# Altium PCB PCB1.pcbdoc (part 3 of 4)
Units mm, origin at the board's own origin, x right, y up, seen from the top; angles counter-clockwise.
Board outline 77.9 x 109.02 mm, 4 copper layers (Top Layer, Inner1, Inner2, Bottom Layer); 129 components, 135 nets, 715 pads, 425 vias.
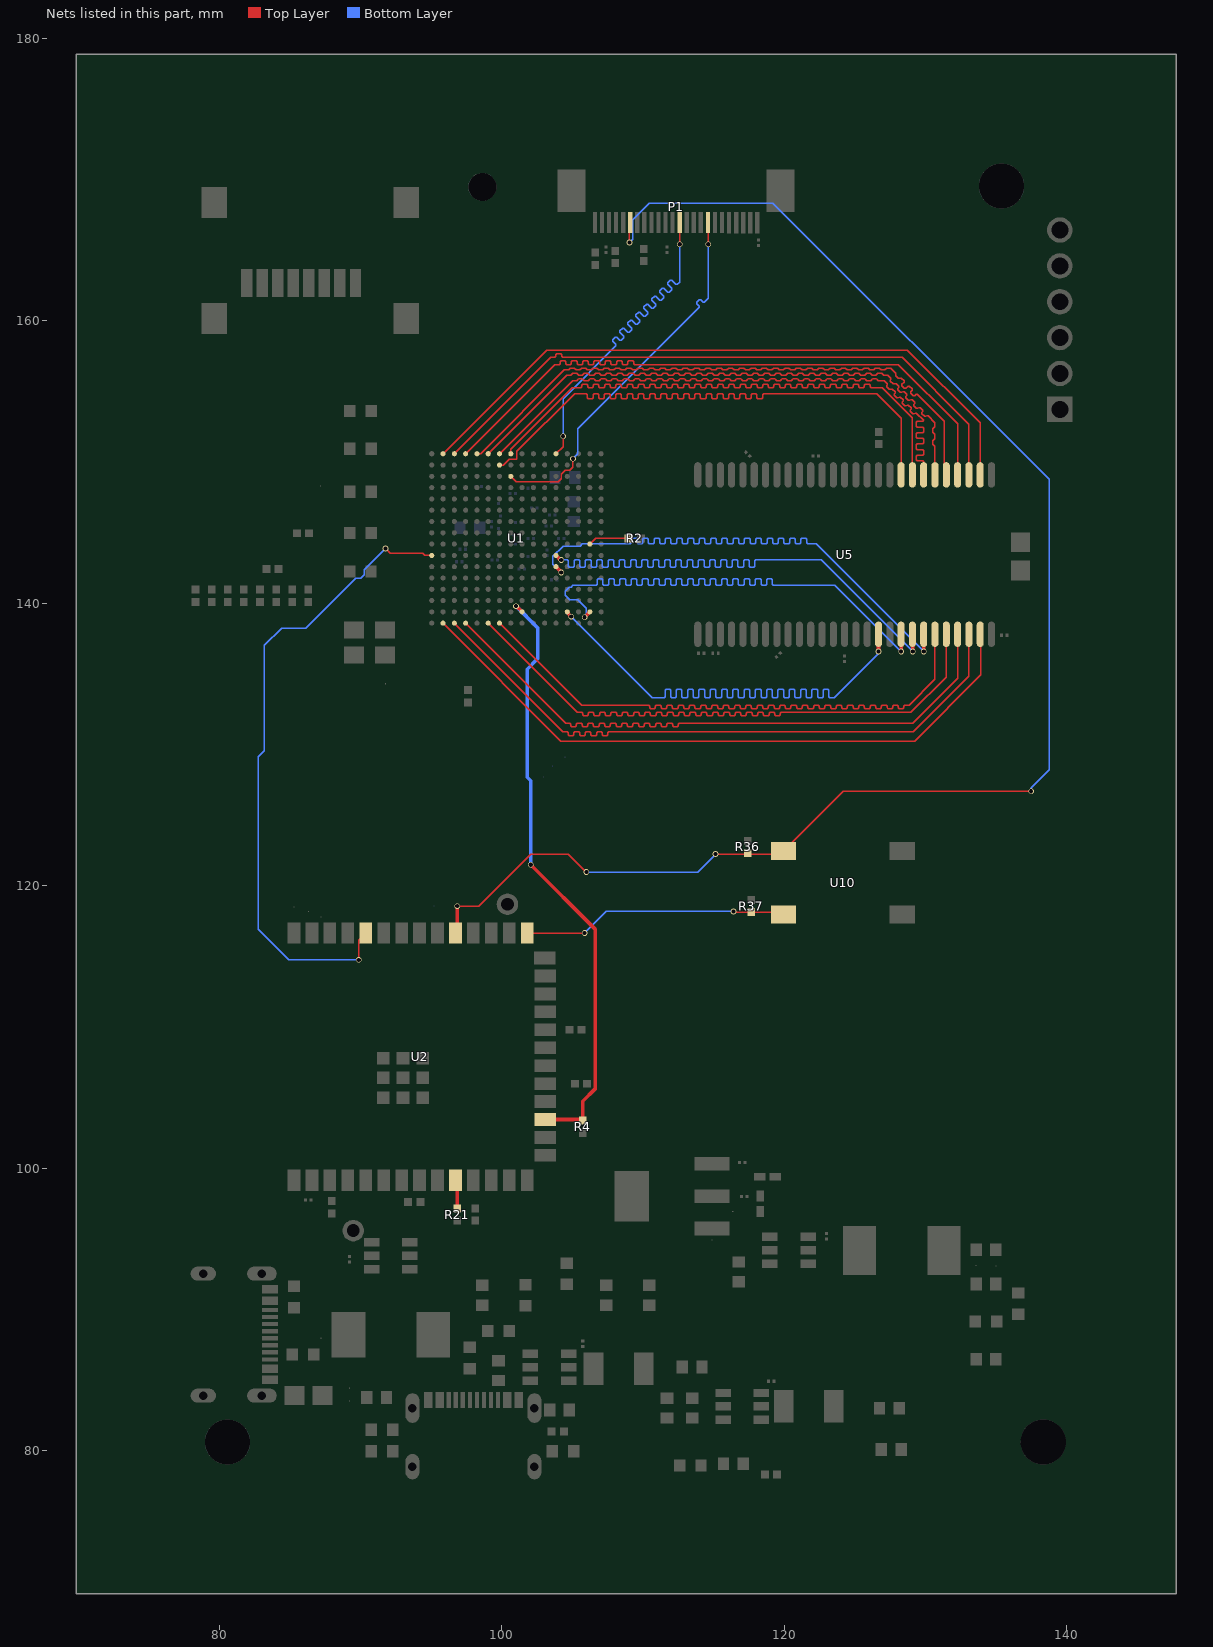
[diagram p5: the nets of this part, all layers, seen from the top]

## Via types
v1: diameter 0.4, hole 0.3, Top Layer to Bottom Layer, 387 vias
v2: diameter 0.5, hole 0.3, Top Layer to Bottom Layer, 36 vias
v3: diameter 1, hole 0.5, Top Layer to Bottom Layer, 2 vias

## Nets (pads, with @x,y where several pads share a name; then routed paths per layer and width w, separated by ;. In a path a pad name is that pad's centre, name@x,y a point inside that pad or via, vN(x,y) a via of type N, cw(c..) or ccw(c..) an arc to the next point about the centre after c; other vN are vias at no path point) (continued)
MCLK: P1.13 U1.A12 | length 27.1
  Top Layer w0.1: U1.A12@103.824,150.585 104.326,151.087 v1(104.326,151.824) ; v1(112.581,165.413) P1.13@112.581,166.951
  Bottom Layer w0.1: v1(104.326,151.824) 104.326,154.491 108.071,158.236 108.071,158.336 107.84,158.567 107.84,158.667 108.023,158.85 108.123,158.85 108.354,158.619 108.454,158.619 108.637,158.802 108.637,158.902 108.356,159.183 108.356,159.283 108.538,159.465 108.638,159.465 108.919,159.184 109.019,159.184 109.202,159.367 109.202,159.467 108.921,159.748 108.921,159.848 109.104,160.031 109.204,160.031 109.485,159.75 109.585,159.75 109.768,159.933 109.768,160.033 109.487,160.314 109.487,160.414 109.67,160.597 109.77,160.597 110.051,160.316 110.151,160.316 110.334,160.499 110.334,160.599 110.053,160.88 110.053,160.98 110.235,161.162 110.335,161.162 110.616,160.881 110.716,160.881 110.899,161.064 110.899,161.164 110.618,161.445 110.618,161.545 110.801,161.728 110.901,161.728 111.182,161.447 111.282,161.447 111.465,161.63 111.465,161.73 111.184,162.011 111.184,162.111 111.367,162.294 111.467,162.294 111.748,162.013 111.848,162.013 112.031,162.196 112.031,162.296 111.75,162.577 111.75,162.677 111.932,162.859 112.032,162.859 112.313,162.578 112.413,162.578 112.581,162.746 v1(112.581,165.413)
PCLK: P1.17 U1.C8 | length 27
  Top Layer w0.1: U1.C8@100.624,148.985 101.006,148.603 103.982,148.603 104.206,148.827 104.206,149.143 104.466,149.403 104.782,149.403 105.006,149.626 105.006,149.943 105.024,149.961 v1(105.024,150.232) ; P1.17@114.581,166.952 114.613,166.92 v1(114.613,165.413)
  Bottom Layer w0.1: v1(105.024,150.232) 105.363,150.571 105.363,152.353 113.952,160.942 113.952,161.042 113.798,161.196 113.798,161.296 113.981,161.479 114.081,161.479 114.235,161.325 114.335,161.325 114.613,161.603 v1(114.613,165.413)
PROGRAM: R37.1 U2.27 U10.3 | length 18.9
  Top Layer w0.1: U2.27@101.781,116.632 105.837,116.632 v1(105.85,116.645) ; v1(116.391,118.169) 116.443,118.117 R37.1@117.661,118.117 119.772,118.117 U10.3@119.938,117.951
  Bottom Layer w0.1: v1(105.85,116.645) 107.374,118.169 v1(116.391,118.169)
PROGRAMN: pad.55@101.786,127.673 R4.2 U1.R9 U2.17 | length 42.9
  Top Layer w0.254: v1(100.987,139.796) 101.013,139.796 U1.R9@101.424,139.385 ; v1(102.04,121.471) 106.59,116.92 106.59,105.591 105.723,104.724 R4.2@105.723,103.362 105.648,103.437 U2.17@103.188,103.437
  Bottom Layer w0.254: v1(100.987,139.796) 102.519,138.264 102.519,136.054 101.786,135.321 pad.55@101.786,127.673 102.04,127.419 v1(102.04,121.471)
RESET: P1.6 R36.1 U2.31 U10.1 | length 110.8
  Top Layer w0.1: v1(96.828,118.55) 98.357,118.55 102.04,122.233 104.707,122.233 v1(105.977,120.963) ; v1(109.025,165.54) 109.025,166.895 P1.6@109.081,166.951 ; v1(115.121,122.233) 119.72,122.233 U10.1@119.938,122.451 124.165,126.678 v1(137.473,126.678)
  Top Layer w0.254: U2.31@96.828,116.632 v1(96.828,118.55)
  Bottom Layer w0.1: v1(105.977,120.963) 113.851,120.963 v1(115.121,122.233) ; v1(109.025,165.54) 109.251,165.766 109.251,167.163 110.422,168.334 119.185,168.334 138.743,148.776 138.743,128.202 137.473,126.932 v1(137.473,126.678)
RX: U1.K1 U2.36 | length 45.5
  Top Layer w0.1: v1(89.848,114.74) 89.848,116.129 U2.36@90.351,116.632 ; v1(91.754,143.878) 92.082,143.55 94.381,143.55 94.546,143.385 U1.K1@95.024,143.385
  Bottom Layer w0.1: v1(89.848,114.74) 84.895,114.74 82.736,116.899 82.736,129.127 83.176,129.567 83.176,137.024 84.387,138.235 86.111,138.235 89.646,141.77 90.014,141.77 90.25,142.005 90.25,142.374 v1(91.754,143.878)
SCL: R21.1 U2.10 | length 1.9
  Top Layer w0.254: U2.10@96.828,99.132 96.833,99.127 R21.1@96.833,97.214
SD_A0: U1.T6 U5.23 | length 45.3
  Top Layer w0.1: U1.T6@99.024,138.585 105.343,132.266 105.643,132.266 105.714,132.195 105.714,132.083 105.784,132.012 106.043,132.012 106.114,132.083 106.114,132.195 106.184,132.266 106.443,132.266 106.514,132.195 106.514,132.083 106.584,132.012 106.843,132.012 106.914,132.083 106.914,132.195 106.984,132.266 107.243,132.266 107.314,132.195 107.314,132.083 107.384,132.012 107.643,132.012 107.714,132.083 107.714,132.195 107.784,132.266 108.043,132.266 108.114,132.195 108.114,132.083 108.184,132.012 108.443,132.012 108.514,132.083 108.514,132.195 108.584,132.266 108.843,132.266 108.914,132.195 108.914,132.083 108.984,132.012 109.243,132.012 109.314,132.083 109.314,132.195 109.384,132.266 109.643,132.266 109.714,132.195 109.714,132.083 109.784,132.012 110.043,132.012 110.114,132.083 110.114,132.195 110.184,132.266 110.443,132.266 110.514,132.195 110.514,132.083 110.584,132.012 110.843,132.012 110.914,132.083 110.914,132.195 110.984,132.266 111.243,132.266 111.314,132.195 111.314,132.083 111.384,132.012 111.643,132.012 111.714,132.083 111.714,132.195 111.784,132.266 112.043,132.266 112.114,132.195 112.114,132.083 112.184,132.012 112.443,132.012 112.514,132.083 112.514,132.195 112.584,132.266 112.843,132.266 112.914,132.195 112.914,132.083 112.984,132.012 113.243,132.012 113.314,132.083 113.314,132.195 113.384,132.266 113.643,132.266 113.714,132.195 113.714,132.083 113.784,132.012 114.043,132.012 114.114,132.083 114.114,132.195 114.184,132.266 114.443,132.266 114.514,132.195 114.514,132.083 114.584,132.012 114.843,132.012 114.914,132.083 114.914,132.195 114.984,132.266 115.243,132.266 115.314,132.195 115.314,132.083 115.384,132.012 115.643,132.012 115.714,132.083 115.714,132.195 115.784,132.266 116.043,132.266 116.114,132.195 116.114,132.083 116.184,132.012 116.443,132.012 116.514,132.083 116.514,132.195 116.584,132.266 116.843,132.266 116.914,132.195 116.914,132.083 116.984,132.012 117.243,132.012 117.314,132.083 117.314,132.195 117.384,132.266 117.643,132.266 117.714,132.195 117.714,132.083 117.784,132.012 118.043,132.012 118.114,132.083 118.114,132.195 118.184,132.266 118.443,132.266 118.514,132.195 118.514,132.083 118.584,132.012 118.843,132.012 118.914,132.083 118.914,132.195 118.984,132.266 119.243,132.266 119.314,132.195 119.314,132.083 119.384,132.012 119.643,132.012 119.714,132.083 119.714,132.195 119.784,132.266 128.964,132.266 131.465,134.767 U5.23@131.465,137.8
SD_A1: U1.T4 U5.24 | length 45.6
  Top Layer w0.1: U1.T4@97.424,138.585 104.505,131.504 104.805,131.504 104.876,131.433 104.876,131.321 104.946,131.25 105.205,131.25 105.276,131.321 105.276,131.433 105.346,131.504 105.605,131.504 105.676,131.433 105.676,131.321 105.746,131.25 106.005,131.25 106.076,131.321 106.076,131.433 106.146,131.504 106.405,131.504 106.476,131.433 106.476,131.321 106.546,131.25 106.805,131.25 106.876,131.321 106.876,131.433 106.946,131.504 107.205,131.504 107.276,131.433 107.276,131.321 107.346,131.25 107.605,131.25 107.676,131.321 107.676,131.433 107.746,131.504 108.005,131.504 108.076,131.433 108.076,131.321 108.146,131.25 108.405,131.25 108.476,131.321 108.476,131.433 108.546,131.504 108.805,131.504 108.876,131.433 108.876,131.321 108.946,131.25 109.205,131.25 109.276,131.321 109.276,131.433 109.346,131.504 109.605,131.504 109.676,131.433 109.676,131.321 109.746,131.25 110.005,131.25 110.076,131.321 110.076,131.433 110.146,131.504 110.405,131.504 110.476,131.433 110.476,131.321 110.546,131.25 110.805,131.25 110.876,131.321 110.876,131.433 110.946,131.504 111.205,131.504 111.276,131.433 111.276,131.321 111.346,131.25 111.605,131.25 111.676,131.321 111.676,131.433 111.746,131.504 112.005,131.504 112.076,131.433 112.076,131.321 112.146,131.25 112.405,131.25 112.476,131.321 112.476,131.433 112.546,131.504 129.091,131.504 132.266,134.679 U5.24@132.266,137.799
SD_A2: U1.T3 U5.25 | length 45.9
  Top Layer w0.1: U1.T3@96.624,138.585 104.303,130.906 104.626,130.906 104.697,130.835 104.697,130.686 104.767,130.615 105.026,130.615 105.097,130.686 105.097,130.835 105.167,130.906 105.426,130.906 105.497,130.835 105.497,130.686 105.567,130.615 105.826,130.615 105.897,130.686 105.897,130.835 105.967,130.906 106.226,130.906 106.297,130.835 106.297,130.686 106.367,130.615 106.626,130.615 106.697,130.686 106.697,130.835 106.767,130.906 107.026,130.906 107.097,130.835 107.097,130.686 107.167,130.615 107.426,130.615 107.497,130.686 107.497,130.835 107.567,130.906 129.128,130.906 133.065,134.843 U5.25@133.065,137.8
SD_A3: U1.T2 U5.26 | length 46.4
  Top Layer w0.1: U1.T2@95.824,138.585 104.175,130.234 129.218,130.234 133.917,134.933 133.917,137.748 U5.26@133.865,137.8
SD_A4: U1.A2 U5.29 | length 46.9
  Top Layer w0.1: U1.A2@95.824,150.585 103.159,157.92 128.71,157.92 133.865,152.765 U5.29@133.865,149.084
SD_A5: U1.A3 U5.30 | length 45.2
  Top Layer w0.1: U1.A3@96.624,150.585 103.451,157.412 103.751,157.412 103.821,157.483 103.821,157.595 103.892,157.666 104.151,157.666 104.221,157.595 104.221,157.483 104.292,157.412 128.329,157.412 133.065,152.676 U5.30@133.065,149.084
SD_A6: U1.A4 U5.31 | length 45.2
  Top Layer w0.1: U1.A4@97.424,150.585 103.743,156.904 104.043,156.904 104.114,156.975 104.114,157.087 104.184,157.158 104.443,157.158 104.514,157.087 104.514,156.975 104.584,156.904 104.843,156.904 104.914,156.975 104.914,157.087 104.984,157.158 105.243,157.158 105.314,157.087 105.314,156.975 105.384,156.904 105.643,156.904 105.714,156.975 105.714,157.087 105.784,157.158 106.043,157.158 106.114,157.087 106.114,156.975 106.184,156.904 106.443,156.904 106.514,156.975 106.514,157.087 106.584,157.158 106.843,157.158 106.914,157.087 106.914,156.975 106.984,156.904 107.243,156.904 107.314,156.975 107.314,157.087 107.384,157.158 107.643,157.158 107.714,157.087 107.714,156.975 107.784,156.904 108.043,156.904 108.114,156.975 108.114,157.087 108.184,157.158 108.443,157.158 108.514,157.087 108.514,156.975 108.584,156.904 108.843,156.904 108.914,156.975 108.914,157.087 108.984,157.158 109.243,157.158 109.314,157.087 109.314,156.975 109.384,156.904 128.075,156.904 132.265,152.714 U5.31@132.265,149.084
SD_A7: U1.A5 U5.32 | length 45.1
  Top Layer w0.1: U1.A5@98.224,150.585 98.484,150.585 104.422,156.523 104.722,156.523 104.849,156.65 105.122,156.65 105.249,156.523 105.522,156.523 105.649,156.65 105.922,156.65 106.049,156.523 106.322,156.523 106.449,156.65 106.722,156.65 106.849,156.523 107.122,156.523 107.249,156.65 107.522,156.65 107.649,156.523 107.922,156.523 108.049,156.65 108.322,156.65 108.449,156.523 108.722,156.523 108.849,156.65 109.122,156.65 109.249,156.523 109.522,156.523 109.649,156.65 109.922,156.65 110.049,156.523 110.322,156.523 110.449,156.65 110.722,156.65 110.849,156.523 111.122,156.523 111.249,156.65 111.522,156.65 111.649,156.523 111.922,156.523 112.049,156.65 112.322,156.65 112.449,156.523 112.722,156.523 112.849,156.65 113.122,156.65 113.249,156.523 113.522,156.523 113.649,156.65 113.922,156.65 114.049,156.523 114.322,156.523 114.449,156.65 114.722,156.65 114.849,156.523 115.122,156.523 115.249,156.65 115.522,156.65 115.649,156.523 115.922,156.523 116.049,156.65 116.322,156.65 116.449,156.523 116.722,156.523 116.849,156.65 117.122,156.65 117.249,156.523 117.522,156.523 117.649,156.65 117.922,156.65 118.049,156.523 118.322,156.523 118.449,156.65 118.722,156.65 118.849,156.523 119.122,156.523 119.249,156.65 119.522,156.65 119.649,156.523 119.922,156.523 120.049,156.65 120.322,156.65 120.449,156.523 120.722,156.523 120.849,156.65 121.122,156.65 121.249,156.523 121.522,156.523 121.649,156.65 121.922,156.65 122.049,156.523 122.322,156.523 122.449,156.65 122.722,156.65 122.849,156.523 123.122,156.523 123.249,156.65 123.522,156.65 123.649,156.523 123.922,156.523 124.049,156.65 124.322,156.65 124.449,156.523 124.722,156.523 124.849,156.65 125.122,156.65 125.249,156.523 125.522,156.523 125.649,156.65 125.922,156.65 126.049,156.523 126.322,156.523 126.449,156.65 126.722,156.65 126.849,156.523 127.122,156.523 127.249,156.65 127.522,156.65 127.894,156.278 127.894,156.099 128.077,155.916 128.177,155.916 128.189,155.928 128.289,155.928 128.472,155.745 128.472,155.645 128.317,155.491 128.317,155.391 128.5,155.208 128.6,155.208 128.754,155.362 128.854,155.362 129.037,155.179 129.037,155.079 128.932,154.974 128.932,154.874 129.114,154.691 129.214,154.691 129.32,154.796 129.42,154.796 131.338,152.879 131.338,149.211 U5.32@131.465,149.084
SD_A8: U1.A6 U5.33 | length 44.4
  Top Layer w0.1: U1.A6@99.024,150.585 104.581,156.142 104.881,156.142 104.952,156.213 104.952,156.223 105.022,156.294 105.281,156.294 105.352,156.223 105.352,156.213 105.422,156.142 105.681,156.142 105.752,156.213 105.752,156.223 105.822,156.294 106.081,156.294 106.152,156.223 106.152,156.213 106.222,156.142 106.481,156.142 106.552,156.213 106.552,156.223 106.622,156.294 106.881,156.294 106.952,156.223 106.952,156.213 107.022,156.142 107.281,156.142 107.352,156.213 107.352,156.223 107.422,156.294 107.681,156.294 107.752,156.223 107.752,156.213 107.822,156.142 108.081,156.142 108.152,156.213 108.152,156.223 108.222,156.294 108.481,156.294 108.552,156.223 108.552,156.213 108.622,156.142 108.881,156.142 108.952,156.213 108.952,156.223 109.022,156.294 109.281,156.294 109.352,156.223 109.352,156.213 109.422,156.142 109.681,156.142 109.752,156.213 109.752,156.223 109.822,156.294 110.081,156.294 110.152,156.223 110.152,156.213 110.222,156.142 110.481,156.142 110.552,156.213 110.552,156.223 110.622,156.294 110.881,156.294 110.952,156.223 110.952,156.213 111.022,156.142 111.281,156.142 111.352,156.213 111.352,156.223 111.422,156.294 111.681,156.294 111.752,156.223 111.752,156.213 111.822,156.142 112.081,156.142 112.152,156.213 112.152,156.223 112.222,156.294 112.481,156.294 112.552,156.223 112.552,156.213 112.622,156.142 112.881,156.142 112.952,156.213 112.952,156.223 113.022,156.294 113.281,156.294 113.352,156.223 113.352,156.213 113.422,156.142 113.681,156.142 113.752,156.213 113.752,156.223 113.822,156.294 114.081,156.294 114.152,156.223 114.152,156.213 114.222,156.142 114.481,156.142 114.552,156.213 114.552,156.223 114.622,156.294 114.881,156.294 114.952,156.223 114.952,156.213 115.022,156.142 115.281,156.142 115.352,156.213 115.352,156.223 115.422,156.294 115.681,156.294 115.752,156.223 115.752,156.213 115.822,156.142 116.081,156.142 116.152,156.213 116.152,156.223 116.222,156.294 116.481,156.294 116.552,156.223 116.552,156.213 116.622,156.142 116.881,156.142 116.952,156.213 116.952,156.223 117.022,156.294 117.281,156.294 117.352,156.223 117.352,156.213 117.422,156.142 117.681,156.142 117.752,156.213 117.752,156.223 117.822,156.294 118.081,156.294 118.152,156.223 118.152,156.213 118.222,156.142 118.481,156.142 118.552,156.213 118.552,156.223 118.622,156.294 118.881,156.294 118.952,156.223 118.952,156.213 119.022,156.142 119.281,156.142 119.352,156.213 119.352,156.223 119.422,156.294 119.681,156.294 119.752,156.223 119.752,156.213 119.822,156.142 120.081,156.142 120.152,156.213 120.152,156.223 120.222,156.294 120.481,156.294 120.552,156.223 120.552,156.213 120.622,156.142 120.881,156.142 120.952,156.213 120.952,156.223 121.022,156.294 121.281,156.294 121.352,156.223 121.352,156.213 121.422,156.142 121.681,156.142 121.752,156.213 121.752,156.223 121.822,156.294 122.081,156.294 122.152,156.223 122.152,156.213 122.222,156.142 122.481,156.142 122.552,156.213 122.552,156.223 122.622,156.294 122.881,156.294 122.952,156.223 122.952,156.213 123.022,156.142 123.281,156.142 123.352,156.213 123.352,156.223 123.422,156.294 123.681,156.294 123.752,156.223 123.752,156.213 123.822,156.142 124.081,156.142 124.152,156.213 124.152,156.223 124.222,156.294 124.481,156.294 124.552,156.223 124.552,156.213 124.622,156.142 124.881,156.142 124.952,156.213 124.952,156.223 125.022,156.294 125.281,156.294 125.352,156.223 125.352,156.213 125.422,156.142 125.681,156.142 125.752,156.213 125.752,156.223 125.822,156.294 126.081,156.294 126.152,156.223 126.152,156.213 126.222,156.142 126.481,156.142 126.552,156.213 126.552,156.223 126.622,156.294 126.881,156.294 126.952,156.223 126.952,156.213 127.022,156.142 127.313,156.142 127.525,155.93 127.525,155.83 127.513,155.818 127.513,155.718 127.696,155.535 127.796,155.535 127.808,155.547 127.908,155.547 128.091,155.364 128.091,155.264 128.035,155.209 128.035,155.109 128.218,154.926 128.318,154.926 128.373,154.981 128.473,154.981 128.656,154.798 128.656,154.698 128.601,154.643 128.601,154.543 128.784,154.36 128.884,154.36 128.939,154.415 129.039,154.415 129.222,154.233 129.222,154.133 129.167,154.077 129.167,153.977 129.349,153.794 129.449,153.794 129.505,153.85 129.605,153.85 129.788,153.667 129.788,153.567 129.741,153.52 129.741,153.42 129.924,153.238 130.024,153.238 130.071,153.284 130.171,153.284 130.665,152.79 130.665,152.49 130.594,152.419 130.577,152.419 130.506,152.348 130.506,152.09 130.577,152.019 130.594,152.019 130.665,151.948 130.665,151.648 130.594,151.578 130.577,151.578 130.506,151.507 130.506,151.248 130.577,151.178 130.594,151.178 130.665,151.107 U5.33@130.665,149.084
SD_A9: U1.A7 U5.34 | length 45.4
  Top Layer w0.1: U1.A7@99.824,150.585 105,155.761 105.3,155.761 105.371,155.832 105.371,155.842 105.441,155.913 105.7,155.913 105.771,155.842 105.771,155.832 105.841,155.761 106.1,155.761 106.171,155.832 106.171,155.842 106.241,155.913 106.5,155.913 106.571,155.842 106.571,155.832 106.641,155.761 106.9,155.761 106.971,155.832 106.971,155.842 107.041,155.913 107.3,155.913 107.371,155.842 107.371,155.832 107.441,155.761 107.7,155.761 107.771,155.832 107.771,155.842 107.841,155.913 108.1,155.913 108.171,155.842 108.171,155.832 108.241,155.761 108.5,155.761 108.571,155.832 108.571,155.842 108.641,155.913 108.9,155.913 108.971,155.842 108.971,155.832 109.041,155.761 109.3,155.761 109.371,155.832 109.371,155.842 109.441,155.913 109.7,155.913 109.771,155.842 109.771,155.832 109.841,155.761 110.1,155.761 110.171,155.832 110.171,155.842 110.241,155.913 110.5,155.913 110.571,155.842 110.571,155.832 110.641,155.761 110.9,155.761 110.971,155.832 110.971,155.842 111.041,155.913 111.3,155.913 111.371,155.842 111.371,155.832 111.441,155.761 111.7,155.761 111.771,155.832 111.771,155.842 111.841,155.913 112.1,155.913 112.171,155.842 112.171,155.832 112.241,155.761 112.5,155.761 112.571,155.832 112.571,155.842 112.641,155.913 112.9,155.913 112.971,155.842 112.971,155.832 113.041,155.761 113.3,155.761 113.371,155.832 113.371,155.842 113.441,155.913 113.7,155.913 113.771,155.842 113.771,155.832 113.841,155.761 114.1,155.761 114.171,155.832 114.171,155.842 114.241,155.913 114.5,155.913 114.571,155.842 114.571,155.832 114.641,155.761 114.9,155.761 114.971,155.832 114.971,155.842 115.041,155.913 115.3,155.913 115.371,155.842 115.371,155.832 115.441,155.761 115.7,155.761 115.771,155.832 115.771,155.842 115.841,155.913 116.1,155.913 116.171,155.842 116.171,155.832 116.241,155.761 116.5,155.761 116.571,155.832 116.571,155.842 116.641,155.913 116.9,155.913 116.971,155.842 116.971,155.832 117.041,155.761 117.3,155.761 117.371,155.832 117.371,155.842 117.441,155.913 117.7,155.913 117.771,155.842 117.771,155.832 117.841,155.761 118.1,155.761 118.171,155.832 118.171,155.842 118.241,155.913 118.5,155.913 118.571,155.842 118.571,155.832 118.641,155.761 118.9,155.761 118.971,155.832 118.971,155.842 119.041,155.913 119.3,155.913 119.371,155.842 119.371,155.832 119.441,155.761 119.7,155.761 119.771,155.832 119.771,155.842 119.841,155.913 120.1,155.913 120.171,155.842 120.171,155.832 120.241,155.761 120.5,155.761 120.571,155.832 120.571,155.842 120.641,155.913 120.9,155.913 120.971,155.842 120.971,155.832 121.041,155.761 121.3,155.761 121.371,155.832 121.371,155.842 121.441,155.913 121.7,155.913 121.771,155.842 121.771,155.832 121.841,155.761 122.1,155.761 122.171,155.832 122.171,155.842 122.241,155.913 122.5,155.913 122.571,155.842 122.571,155.832 122.641,155.761 122.9,155.761 122.971,155.832 122.971,155.842 123.041,155.913 123.3,155.913 123.371,155.842 123.371,155.832 123.441,155.761 123.7,155.761 123.771,155.832 123.771,155.842 123.841,155.913 124.1,155.913 124.171,155.842 124.171,155.832 124.241,155.761 124.5,155.761 124.571,155.832 124.571,155.842 124.641,155.913 124.9,155.913 124.971,155.842 124.971,155.832 125.041,155.761 125.3,155.761 125.371,155.832 125.371,155.842 125.441,155.913 125.7,155.913 125.771,155.842 125.771,155.832 125.841,155.761 126.1,155.761 126.171,155.832 126.171,155.842 126.241,155.913 126.5,155.913 126.571,155.842 126.571,155.832 126.641,155.761 127.059,155.761 127.271,155.549 127.271,155.449 127.259,155.437 127.259,155.337 127.442,155.154 127.542,155.154 127.554,155.166 127.654,155.166 127.837,154.983 127.837,154.883 127.781,154.828 127.781,154.728 127.964,154.545 128.064,154.545 128.119,154.6 128.219,154.6 128.402,154.417 128.402,154.317 128.347,154.262 128.347,154.162 128.53,153.979 128.63,153.979 128.685,154.034 128.785,154.034 128.968,153.852 128.968,153.752 128.913,153.696 128.913,153.596 129.095,153.413 129.195,153.413 129.251,153.469 129.351,153.469 129.865,152.955 129.865,152.947 129.794,152.876 129.416,152.876 129.345,152.805 129.345,152.547 129.416,152.476 129.794,152.476 129.865,152.405 129.865,152.147 129.794,152.076 129.416,152.076 129.345,152.005 129.345,151.747 129.416,151.676 129.794,151.676 129.865,151.605 129.865,151.347 129.794,151.276 129.416,151.276 129.345,151.205 129.345,150.947 129.416,150.876 129.794,150.876 129.865,150.805 129.865,150.547 129.794,150.476 129.416,150.476 129.345,150.405 129.345,150.147 129.416,150.076 129.794,150.076 129.865,150.005 U5.34@129.865,149.084
SD_A10: U1.T7 U5.22 | length 45.1
  Top Layer w0.1: U1.T7@99.824,138.585 105.635,132.774 110.395,132.774 110.466,132.703 110.466,132.591 110.537,132.52 110.795,132.52 110.866,132.591 110.866,132.703 110.937,132.774 111.195,132.774 111.266,132.703 111.266,132.591 111.337,132.52 111.595,132.52 111.666,132.591 111.666,132.703 111.737,132.774 111.995,132.774 112.066,132.703 112.066,132.591 112.137,132.52 112.395,132.52 112.466,132.591 112.466,132.703 112.537,132.774 112.795,132.774 112.866,132.703 112.866,132.591 112.937,132.52 113.195,132.52 113.266,132.591 113.266,132.703 113.337,132.774 113.595,132.774 113.666,132.703 113.666,132.591 113.737,132.52 113.995,132.52 114.066,132.591 114.066,132.703 114.137,132.774 114.395,132.774 114.466,132.703 114.466,132.591 114.537,132.52 114.795,132.52 114.866,132.591 114.866,132.703 114.937,132.774 115.195,132.774 115.266,132.703 115.266,132.591 115.337,132.52 115.595,132.52 115.666,132.591 115.666,132.703 115.737,132.774 115.995,132.774 116.066,132.703 116.066,132.591 116.137,132.52 116.395,132.52 116.466,132.591 116.466,132.703 116.537,132.774 116.795,132.774 116.866,132.703 116.866,132.591 116.937,132.52 117.195,132.52 117.266,132.591 117.266,132.703 117.337,132.774 117.595,132.774 117.666,132.703 117.666,132.591 117.737,132.52 117.995,132.52 118.066,132.591 118.066,132.703 118.137,132.774 118.395,132.774 118.466,132.703 118.466,132.591 118.537,132.52 118.795,132.52 118.866,132.591 118.866,132.703 118.937,132.774 119.195,132.774 119.266,132.703 119.266,132.591 119.337,132.52 119.595,132.52 119.666,132.591 119.666,132.703 119.737,132.774 119.995,132.774 120.066,132.703 120.066,132.591 120.137,132.52 120.395,132.52 120.466,132.591 120.466,132.703 120.537,132.774 120.795,132.774 120.866,132.703 120.866,132.591 120.937,132.52 121.195,132.52 121.266,132.591 121.266,132.703 121.337,132.774 121.595,132.774 121.666,132.703 121.666,132.591 121.737,132.52 121.995,132.52 122.066,132.591 122.066,132.703 122.137,132.774 122.395,132.774 122.466,132.703 122.466,132.591 122.537,132.52 122.795,132.52 122.866,132.591 122.866,132.703 122.937,132.774 123.195,132.774 123.266,132.703 123.266,132.591 123.337,132.52 123.595,132.52 123.666,132.591 123.666,132.703 123.737,132.774 123.995,132.774 124.066,132.703 124.066,132.591 124.137,132.52 124.395,132.52 124.466,132.591 124.466,132.703 124.537,132.774 124.795,132.774 124.866,132.703 124.866,132.591 124.937,132.52 125.195,132.52 125.266,132.591 125.266,132.703 125.337,132.774 125.595,132.774 125.666,132.703 125.666,132.591 125.737,132.52 125.995,132.52 126.066,132.591 126.066,132.703 126.137,132.774 126.395,132.774 126.466,132.703 126.466,132.591 126.537,132.52 126.795,132.52 126.866,132.591 126.866,132.703 126.937,132.774 127.195,132.774 127.266,132.703 127.266,132.591 127.337,132.52 127.595,132.52 127.666,132.591 127.666,132.703 127.737,132.774 127.995,132.774 128.066,132.703 128.066,132.591 128.137,132.52 128.395,132.52 128.466,132.591 128.466,132.703 128.537,132.774 128.837,132.774 130.665,134.602 U5.22@130.665,137.8
SD_A11: U1.A8 U5.35 | length 44.4
  Top Layer w0.1: U1.A8@100.624,150.585 100.624,150.916 104.961,155.253 105.592,155.253 105.662,155.324 105.662,155.436 105.733,155.507 105.992,155.507 106.062,155.436 106.062,155.324 106.133,155.253 106.392,155.253 106.462,155.324 106.462,155.436 106.533,155.507 106.792,155.507 106.862,155.436 106.862,155.324 106.933,155.253 107.192,155.253 107.262,155.324 107.262,155.436 107.333,155.507 107.592,155.507 107.662,155.436 107.662,155.324 107.733,155.253 107.992,155.253 108.062,155.324 108.062,155.436 108.133,155.507 108.392,155.507 108.462,155.436 108.462,155.324 108.533,155.253 108.792,155.253 108.862,155.324 108.862,155.436 108.933,155.507 109.192,155.507 109.262,155.436 109.262,155.324 109.333,155.253 109.592,155.253 109.662,155.324 109.662,155.436 109.733,155.507 109.992,155.507 110.062,155.436 110.062,155.324 110.133,155.253 110.392,155.253 110.462,155.324 110.462,155.436 110.533,155.507 110.792,155.507 110.862,155.436 110.862,155.324 110.933,155.253 111.192,155.253 111.262,155.324 111.262,155.436 111.333,155.507 111.592,155.507 111.662,155.436 111.662,155.324 111.733,155.253 111.992,155.253 112.062,155.324 112.062,155.436 112.133,155.507 112.392,155.507 112.462,155.436 112.462,155.324 112.533,155.253 112.792,155.253 112.862,155.324 112.862,155.436 112.933,155.507 113.192,155.507 113.262,155.436 113.262,155.324 113.333,155.253 113.592,155.253 113.662,155.324 113.662,155.436 113.733,155.507 113.992,155.507 114.062,155.436 114.062,155.324 114.133,155.253 114.392,155.253 114.462,155.324 114.462,155.436 114.533,155.507 114.792,155.507 114.862,155.436 114.862,155.324 114.933,155.253 115.192,155.253 115.262,155.324 115.262,155.436 115.333,155.507 115.592,155.507 115.662,155.436 115.662,155.324 115.733,155.253 115.992,155.253 116.062,155.324 116.062,155.436 116.133,155.507 116.392,155.507 116.462,155.436 116.462,155.324 116.533,155.253 116.792,155.253 116.862,155.324 116.862,155.436 116.933,155.507 117.192,155.507 117.262,155.436 117.262,155.324 117.333,155.253 117.592,155.253 117.662,155.324 117.662,155.436 117.733,155.507 117.992,155.507 118.062,155.436 118.062,155.324 118.133,155.253 118.392,155.253 118.462,155.324 118.462,155.436 118.533,155.507 118.792,155.507 118.862,155.436 118.862,155.324 118.933,155.253 119.192,155.253 119.262,155.324 119.262,155.436 119.333,155.507 119.592,155.507 119.662,155.436 119.662,155.324 119.733,155.253 119.992,155.253 120.062,155.324 120.062,155.436 120.133,155.507 120.392,155.507 120.462,155.436 120.462,155.324 120.533,155.253 120.792,155.253 120.862,155.324 120.862,155.436 120.933,155.507 121.192,155.507 121.262,155.436 121.262,155.324 121.333,155.253 121.592,155.253 121.662,155.324 121.662,155.436 121.733,155.507 121.992,155.507 122.062,155.436 122.062,155.324 122.133,155.253 122.392,155.253 122.462,155.324 122.462,155.436 122.533,155.507 122.792,155.507 122.862,155.436 122.862,155.324 122.933,155.253 123.192,155.253 123.262,155.324 123.262,155.436 123.333,155.507 123.592,155.507 123.662,155.436 123.662,155.324 123.733,155.253 123.992,155.253 124.062,155.324 124.062,155.436 124.133,155.507 124.392,155.507 124.462,155.436 124.462,155.324 124.533,155.253 124.792,155.253 124.862,155.324 124.862,155.436 124.933,155.507 125.192,155.507 125.262,155.436 125.262,155.324 125.333,155.253 125.592,155.253 125.662,155.324 125.662,155.436 125.733,155.507 125.992,155.507 126.062,155.436 126.062,155.324 126.133,155.253 126.932,155.253 129.065,153.12 U5.35@129.065,149.084
SD_A12: U1.B7 U5.36 | length 45.1
  Top Layer w0.1: U1.B7@99.824,149.785 100.084,149.785 100.502,150.203 101.016,150.203 101.042,150.228 101.042,150.743 105.144,154.845 105.984,154.845 106.055,154.774 106.055,154.535 106.125,154.464 106.384,154.464 106.455,154.535 106.455,154.774 106.525,154.845 106.784,154.845 106.855,154.774 106.855,154.535 106.925,154.464 107.184,154.464 107.255,154.535 107.255,154.774 107.325,154.845 107.584,154.845 107.655,154.774 107.655,154.535 107.725,154.464 107.984,154.464 108.055,154.535 108.055,154.774 108.125,154.845 108.384,154.845 108.455,154.774 108.455,154.535 108.525,154.464 108.784,154.464 108.855,154.535 108.855,154.774 108.925,154.845 109.184,154.845 109.255,154.774 109.255,154.535 109.325,154.464 109.584,154.464 109.655,154.535 109.655,154.774 109.725,154.845 109.984,154.845 110.055,154.774 110.055,154.535 110.125,154.464 110.384,154.464 110.455,154.535 110.455,154.774 110.525,154.845 110.784,154.845 110.855,154.774 110.855,154.535 110.925,154.464 111.184,154.464 111.255,154.535 111.255,154.774 111.325,154.845 111.584,154.845 111.655,154.774 111.655,154.535 111.725,154.464 111.984,154.464 112.055,154.535 112.055,154.774 112.125,154.845 112.384,154.845 112.455,154.774 112.455,154.535 112.525,154.464 112.784,154.464 112.855,154.535 112.855,154.774 112.925,154.845 113.184,154.845 113.255,154.774 113.255,154.535 113.325,154.464 113.584,154.464 113.655,154.535 113.655,154.774 113.725,154.845 113.984,154.845 114.055,154.774 114.055,154.535 114.125,154.464 114.384,154.464 114.455,154.535 114.455,154.774 114.525,154.845 114.784,154.845 114.855,154.774 114.855,154.535 114.925,154.464 115.184,154.464 115.255,154.535 115.255,154.774 115.325,154.845 115.584,154.845 115.655,154.774 115.655,154.535 115.725,154.464 115.984,154.464 116.055,154.535 116.055,154.774 116.125,154.845 116.384,154.845 116.455,154.774 116.455,154.535 116.525,154.464 116.784,154.464 116.855,154.535 116.855,154.774 116.925,154.845 117.184,154.845 117.255,154.774 117.255,154.535 117.325,154.464 117.584,154.464 117.655,154.535 117.655,154.774 117.725,154.845 117.984,154.845 118.055,154.774 118.055,154.535 118.125,154.464 118.384,154.464 118.455,154.535 118.455,154.774 118.525,154.845 126.524,154.845 128.265,153.104 U5.36@128.265,149.084
SD_BA0: U1.K12 U5.20 | length 43.4
  Top Layer w0.254: U1.K12@103.824,143.385 104.15,143.059 v1(104.197,143.059) ; U5.20@129.065,137.8 129.091,137.774 v1(129.091,136.584)
  Bottom Layer w0.1: v1(104.197,143.059) 104.638,143.059 104.709,142.988 104.709,142.633 104.78,142.562 105.038,142.562 105.109,142.633 105.109,142.988 105.18,143.059 105.438,143.059 105.509,142.988 105.509,142.633 105.58,142.562 105.838,142.562 105.909,142.633 105.909,142.988 105.98,143.059 106.238,143.059 106.309,142.988 106.309,142.633 106.38,142.562 106.638,142.562 106.709,142.633 106.709,142.988 106.78,143.059 107.038,143.059 107.109,142.988 107.109,142.633 107.18,142.562 107.438,142.562 107.509,142.633 107.509,142.988 107.58,143.059 107.838,143.059 107.909,142.988 107.909,142.633 107.98,142.562 108.238,142.562 108.309,142.633 108.309,142.988 108.38,143.059 108.638,143.059 108.709,142.988 108.709,142.633 108.78,142.562 109.038,142.562 109.109,142.633 109.109,142.988 109.18,143.059 109.438,143.059 109.509,142.988 109.509,142.633 109.58,142.562 109.838,142.562 109.909,142.633 109.909,142.988 109.98,143.059 110.238,143.059 110.309,142.988 110.309,142.633 110.38,142.562 110.638,142.562 110.709,142.633 110.709,142.988 110.78,143.059 111.038,143.059 111.109,142.988 111.109,142.633 111.18,142.562 111.438,142.562 111.509,142.633 111.509,142.988 111.58,143.059 111.838,143.059 111.909,142.988 111.909,142.633 111.98,142.562 112.238,142.562 112.309,142.633 112.309,142.988 112.38,143.059 112.638,143.059 112.709,142.988 112.709,142.633 112.78,142.562 113.038,142.562 113.109,142.633 113.109,142.988 113.18,143.059 113.438,143.059 113.509,142.988 113.509,142.633 113.58,142.562 113.838,142.562 113.909,142.633 113.909,142.988 113.98,143.059 114.238,143.059 114.309,142.988 114.309,142.633 114.38,142.562 114.638,142.562 114.709,142.633 114.709,142.988 114.78,143.059 115.038,143.059 115.109,142.988 115.109,142.633 115.18,142.562 115.438,142.562 115.509,142.633 115.509,142.988 115.58,143.059 115.838,143.059 115.909,142.988 115.909,142.633 115.98,142.562 116.238,142.562 116.309,142.633 116.309,142.988 116.38,143.059 116.638,143.059 116.709,142.988 116.709,142.633 116.78,142.562 117.038,142.562 117.109,142.633 117.109,142.988 117.18,143.059 117.438,143.059 117.509,142.988 117.509,142.633 117.58,142.562 117.838,142.562 117.909,142.633 117.909,142.988 117.98,143.059 122.615,143.059 v1(129.091,136.584)
SD_BA1: U1.L12 U5.21 | length 42.5
  Top Layer w0.254: U1.L12@103.824,142.585 104.199,142.21 v1(104.199,142.172) ; v1(129.865,136.584) U5.21@129.865,137.8
  Bottom Layer w0.1: v1(104.199,142.172) 103.595,142.775 103.595,143.309 104.335,144.049 105.528,144.049 105.683,144.204 109.098,144.204 109.169,144.275 109.169,144.514 109.24,144.585 109.498,144.585 109.569,144.514 109.569,144.275 109.64,144.204 109.898,144.204 109.969,144.275 109.969,144.514 110.04,144.585 110.298,144.585 110.369,144.514 110.369,144.275 110.44,144.204 110.698,144.204 110.769,144.275 110.769,144.514 110.84,144.585 111.098,144.585 111.169,144.514 111.169,144.275 111.24,144.204 111.498,144.204 111.569,144.275 111.569,144.514 111.64,144.585 111.898,144.585 111.969,144.514 111.969,144.275 112.04,144.204 112.298,144.204 112.369,144.275 112.369,144.514 112.44,144.585 112.698,144.585 112.769,144.514 112.769,144.275 112.84,144.204 113.098,144.204 113.169,144.275 113.169,144.514 113.24,144.585 113.498,144.585 113.569,144.514 113.569,144.275 113.64,144.204 113.898,144.204 113.969,144.275 113.969,144.514 114.04,144.585 114.298,144.585 114.369,144.514 114.369,144.275 114.44,144.204 114.698,144.204 114.769,144.275 114.769,144.514 114.84,144.585 115.098,144.585 115.169,144.514 115.169,144.275 115.24,144.204 115.498,144.204 115.569,144.275 115.569,144.514 115.64,144.585 115.898,144.585 115.969,144.514 115.969,144.275 116.04,144.204 116.298,144.204 116.369,144.275 116.369,144.514 116.44,144.585 116.698,144.585 116.769,144.514 116.769,144.275 116.84,144.204 117.098,144.204 117.169,144.275 117.169,144.514 117.24,144.585 117.498,144.585 117.569,144.514 117.569,144.275 117.64,144.204 117.898,144.204 117.969,144.275 117.969,144.514 118.04,144.585 118.298,144.585 118.369,144.514 118.369,144.275 118.44,144.204 118.698,144.204 118.769,144.275 118.769,144.514 118.84,144.585 119.098,144.585 119.169,144.514 119.169,144.275 119.24,144.204 119.498,144.204 119.569,144.275 119.569,144.514 119.64,144.585 119.898,144.585 119.969,144.514 119.969,144.275 120.04,144.204 120.298,144.204 120.369,144.275 120.369,144.514 120.44,144.585 120.698,144.585 120.769,144.514 120.769,144.275 120.84,144.204 121.098,144.204 121.169,144.275 121.169,144.514 121.24,144.585 121.498,144.585 121.569,144.514 121.569,144.275 121.64,144.204 122.245,144.204 v1(129.865,136.584)
SD_CAS_N: U1.R13 U5.17 | length 43.1
  Top Layer w0.254: U1.R13@104.624,139.385 104.624,139.337 v1(104.912,139.049) ; v1(126.665,136.584) U5.17@126.665,137.8
  Bottom Layer w0.1: v1(104.912,139.049) 110.656,133.305 111.476,133.305 111.546,133.376 111.546,133.846 111.617,133.917 111.876,133.917 111.946,133.846 111.946,133.376 112.017,133.305 112.276,133.305 112.346,133.376 112.346,133.846 112.417,133.917 112.676,133.917 112.746,133.846 112.746,133.376 112.817,133.305 113.076,133.305 113.146,133.376 113.146,133.846 113.217,133.917 113.476,133.917 113.546,133.846 113.546,133.376 113.617,133.305 113.876,133.305 113.946,133.376 113.946,133.846 114.017,133.917 114.276,133.917 114.346,133.846 114.346,133.376 114.417,133.305 114.676,133.305 114.746,133.376 114.746,133.846 114.817,133.917 115.076,133.917 115.146,133.846 115.146,133.376 115.217,133.305 115.476,133.305 115.546,133.376 115.546,133.846 115.617,133.917 115.876,133.917 115.946,133.846 115.946,133.376 116.017,133.305 116.276,133.305 116.346,133.376 116.346,133.846 116.417,133.917 116.676,133.917 116.746,133.846 116.746,133.376 116.817,133.305 117.076,133.305 117.146,133.376 117.146,133.846 117.217,133.917 117.476,133.917 117.546,133.846 117.546,133.376 117.617,133.305 117.876,133.305 117.946,133.376 117.946,133.846 118.017,133.917 118.276,133.917 118.346,133.846 118.346,133.376 118.417,133.305 118.676,133.305 118.746,133.376 118.746,133.846 118.817,133.917 119.076,133.917 119.146,133.846 119.146,133.376 119.217,133.305 119.476,133.305 119.546,133.376 119.546,133.846 119.617,133.917 119.876,133.917 119.946,133.846 119.946,133.376 120.017,133.305 120.276,133.305 120.346,133.376 120.346,133.846 120.417,133.917 120.676,133.917 120.746,133.846 120.746,133.376 120.817,133.305 121.076,133.305 121.146,133.376 121.146,133.846 121.217,133.917 121.476,133.917 121.546,133.846 121.546,133.376 121.617,133.305 121.876,133.305 121.946,133.376 121.946,133.846 122.017,133.917 122.276,133.917 122.346,133.846 122.346,133.376 122.417,133.305 122.676,133.305 122.746,133.376 122.746,133.846 122.817,133.917 123.076,133.917 123.146,133.846 123.146,133.376 123.217,133.305 123.517,133.305 126.665,136.452 v1(126.665,136.584)
SD_CLK: R2.2 U1.J15 | length 2.9
  Top Layer w0.1: U1.J15@106.224,144.185 106.624,144.585 R2.2@108.973,144.585
SD_CS_N: U1.R15 U5.19 | length 43
  Top Layer w0.254: v1(105.85,138.997) 106.224,139.371 U1.R15@106.224,139.385 ; v1(128.265,136.584) U5.19@128.265,137.8
  Bottom Layer w0.1: v1(105.85,138.997) 105.977,138.997 105.977,139.632 105.363,140.246 104.794,140.246 104.482,140.558 104.482,140.846 104.762,141.127 104.889,141.127 105.016,141.254 106.677,141.254 106.747,141.325 106.747,141.654 106.818,141.725 107.077,141.725 107.147,141.654 107.147,141.325 107.218,141.254 107.477,141.254 107.547,141.325 107.547,141.654 107.618,141.725 107.877,141.725 107.947,141.654 107.947,141.325 108.018,141.254 108.277,141.254 108.347,141.325 108.347,141.654 108.418,141.725 108.677,141.725 108.747,141.654 108.747,141.325 108.818,141.254 109.077,141.254 109.147,141.325 109.147,141.654 109.218,141.725 109.477,141.725 109.547,141.654 109.547,141.325 109.618,141.254 109.877,141.254 109.947,141.325 109.947,141.654 110.018,141.725 110.277,141.725 110.347,141.654 110.347,141.325 110.418,141.254 110.677,141.254 110.747,141.325 110.747,141.654 110.818,141.725 111.077,141.725 111.147,141.654 111.147,141.325 111.218,141.254 111.477,141.254 111.547,141.325 111.547,141.654 111.618,141.725 111.877,141.725 111.947,141.654 111.947,141.325 112.018,141.254 112.277,141.254 112.347,141.325 112.347,141.654 112.418,141.725 112.677,141.725 112.747,141.654 112.747,141.325 112.818,141.254 113.077,141.254 113.147,141.325 113.147,141.654 113.218,141.725 113.477,141.725 113.547,141.654 113.547,141.325 113.618,141.254 113.877,141.254 113.947,141.325 113.947,141.654 114.018,141.725 114.277,141.725 114.347,141.654 114.347,141.325 114.418,141.254 114.677,141.254 114.747,141.325 114.747,141.654 114.818,141.725 115.077,141.725 115.147,141.654 115.147,141.325 115.218,141.254 115.477,141.254 115.547,141.325 115.547,141.654 115.618,141.725 115.877,141.725 115.947,141.654 115.947,141.325 116.018,141.254 116.277,141.254 116.347,141.325 116.347,141.654 116.418,141.725 116.677,141.725 116.747,141.654 116.747,141.325 116.818,141.254 117.077,141.254 117.147,141.325 117.147,141.654 117.218,141.725 117.477,141.725 117.547,141.654 117.547,141.325 117.618,141.254 117.877,141.254 117.947,141.325 117.947,141.654 118.018,141.725 118.277,141.725 118.347,141.654 118.347,141.325 118.418,141.254 118.677,141.254 118.747,141.325 118.747,141.654 118.818,141.725 119.077,141.725 119.147,141.654 119.147,141.325 119.218,141.254 123.574,141.254 128.117,136.711 128.138,136.711 v1(128.265,136.584)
